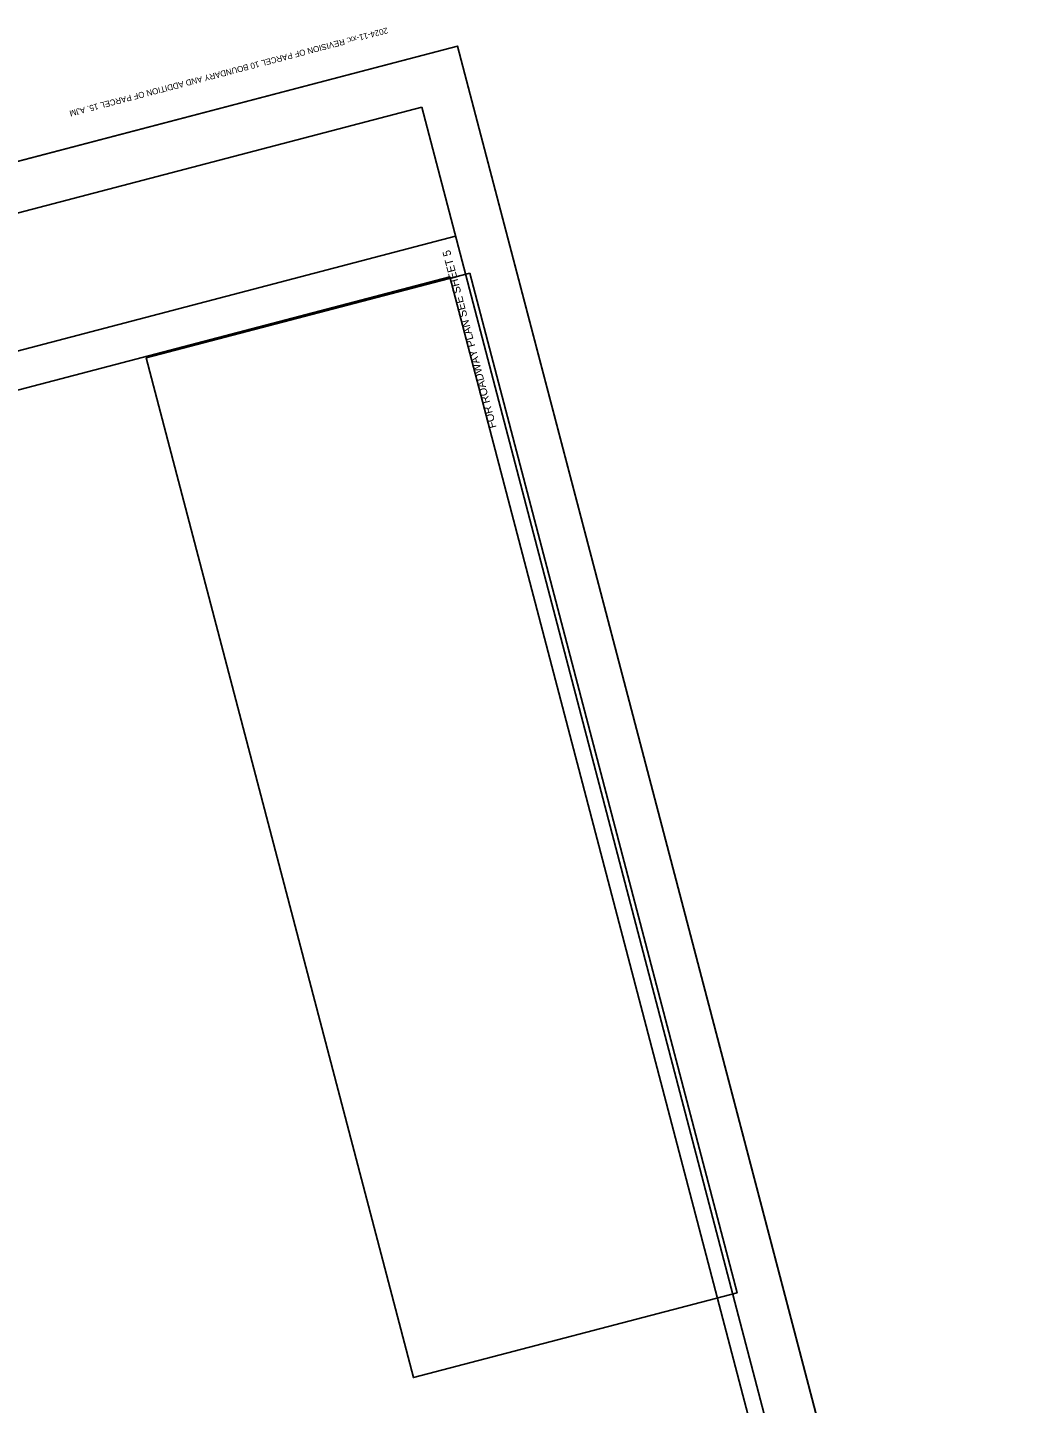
# Model space of a CAD drawing. Extents: x 1366396 to 1367943, y 879298 to 881235.
# Drawn here: x 1367149 to 1367903, y 880204 to 881235 of the extents above; entities that cross this region are included whole.
import ezdxf

# ---------------------------------------------------------------- set-up
doc = ezdxf.new("R2010")
doc.units = 0
for name, color, linetype in [('Draft_RDY_Construction_Class_Element', 7, 'Continuous'), ('Old_Level_1', 7, 'Continuous'), ('Prop Easement Permanent Drainage Utility Station Offsets', 7, 'Continuous'), ('Prop GRAU CAT1 Cell', 7, 'Continuous'), ('Prop Structure Anchor Unit CELL', 7, 'Continuous'), ('Prop Superelevation Label', 7, 'Continuous'), ('Sheet_Plot_Border_Outside_CELL', 7, 'Continuous')]:
    doc.layers.add(name, color=color, linetype=linetype)

msp = doc.modelspace()

# ---------------------------------------------------------------- linework, layer by layer
at = {"layer": 'Draft_RDY_Construction_Class_Element'}
msp.add_lwpolyline([(1366838.5, 879297.8), (1366407.5, 880942.3), (1367471.6, 881221.1), (1367902.6, 879576.7)], close=True, dxfattribs=at)
at = {"layer": 'Old_Level_1'}
for p, q in [((1367471.6, 881221.1), (1366407.5, 880942.3)), ((1367902.6, 879576.7), (1367471.6, 881221.1))]:
    msp.add_line(p, q, dxfattribs=at)
at = {"layer": 'Prop Easement Permanent Drainage Utility Station Offsets'}
msp.add_lwpolyline([(1367480.8, 881051), (1367681.1, 880286.7), (1367438.6, 880223.1), (1367238.3, 880987.5)], close=True, dxfattribs=at)
at = {"layer": 'Prop GRAU CAT1 Cell'}
msp.add_lwpolyline([(1366870, 879396.1), (1366503.2, 880795.9), (1367465.8, 881048.1), (1367814.9, 879716.1)], close=True, dxfattribs=at)
at = {"layer": 'Prop Superelevation Label'}
for p, q in [((1367444.8, 881175.3), (1366453.3, 880915.5)), ((1367856.8, 879603.4), (1367444.8, 881175.3)), ((1367470.2, 881078.6), (1366478.7, 880818.8))]:
    msp.add_line(p, q, dxfattribs=at)

# ---------------------------------------------------------------- texts
at = {"layer": 'Prop Structure Anchor Unit CELL'}
msp.add_text('2024-11-xx: REVISION OF PARCEL 10 BOUNDARY AND ADDITION OF PARCEL 15. AJM', height=4.501, rotation=194.6851, dxfattribs=at).set_placement((1367418.8, 881235.1))
at = {"layer": 'Sheet_Plot_Border_Outside_CELL'}
msp.add_text('FOR ROADWAY PLAN SEE SHEET 5', height=6, rotation=104.6851, dxfattribs=at).set_placement((1367500.9, 880935.4))

doc.saveas('drawing.dxf')
